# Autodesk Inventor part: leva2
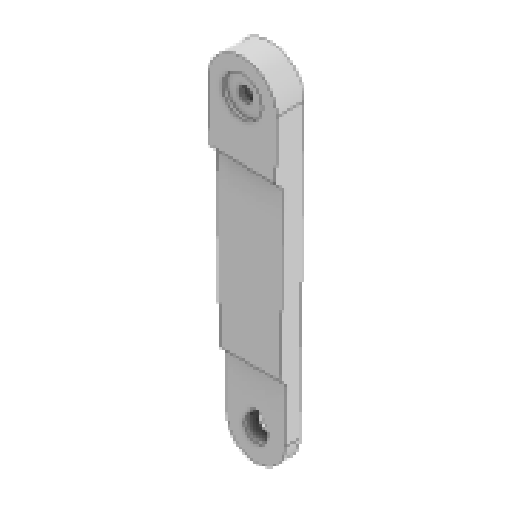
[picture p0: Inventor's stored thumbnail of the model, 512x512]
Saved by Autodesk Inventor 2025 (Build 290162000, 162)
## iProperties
Created: 2025-05
Part Number: leva2
Material: Plastica ABS
Document SubType Name: Modeling
Designer: R5800u
Density: 1.06 g/cm^3
Appearance: Liscia - Nero
Author: R5800u
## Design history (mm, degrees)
sketch "Schizzo1"
  geometry: L1 (-17.498, 149.708)-(-14.998, -0.25); L2 (17.498, 149.708)-(14.998, -0.25); L3 (0, 0)-(0, 150); A1 r 15 centre (0, 0) between (-14.998, -0.25) and (14.998, -0.25); A2 r 17.5 centre (0, 150) between (-17.498, 149.708) and (17.498, 149.708); 1 further point
  constraints: 6 end point, 4 point on circle, 4 tangent, 2 centre point, 2 coincident, 1 vertical
  dimensions: "d0" = 30 diameter of A1; "d1" = 35 diameter of A2; "d28" = 150 distance of L3.start L3.end
extrude "Estrusione1" new body sketch "Schizzo1" distance "d3" = 10; taper "d4" = 0 deg
sketch "Schizzo2"
  geometry: L1 (-17.498, 149.708)-(-14.998, -0.25) reference; L2 (14.998, -0.25)-(17.498, 149.708) reference; L3 (-17.498, 149.708)-(-14.998, -0.25) reference; L4 (-17.007, 120.279)-(16.998, 119.713); A1 r 15 centre (0, 0) between (-14.998, -0.25) and (14.998, -0.25) reference; A2 r 17.5 centre (0, 150) between (17.498, 149.708) and (-17.498, 149.708) reference; 2 further points
  constraints: 2 end point, 2 point on line, 1 perpendicular
  dimensions: "d5" = 30 distance from line of L4 A2.centre
extrude "Estrusione2" join sketch "Schizzo2" distance "d6" = 4; taper "d7" = 0 deg
sketch "Schizzo3"
  geometry: C1 r 10 at (0, 150); A1 r 17.5 centre (0, 150) between (17.498, 149.708) and (-17.498, 149.708) reference; 1 further point
  constraints: 1 centre point, 1 coincident
  dimensions: "d8" = 20 diameter of C1
extrude "Estrusione3" cut sketch "Schizzo3" distance "d9" = 2; taper "d10" = 0 deg
sketch "Schizzo4"
  geometry: C1 r 10 at (0, 0) reference; 2 further points
  constraints: 1 coincident
hole "Foro1" sketch "Schizzo4" at (0, 0) diameter "d11" = 3.2; stored, may be unused: countersink angle "d15" = 90 deg, drill point angle "d17" = 118 deg; dims "d12" = 6, "d13" = 7, "d14" = 3, "d16" = 8
chamfer "Smusso1" distance "d18" = 4; stored, may be unused: second distance "d19" = 2, angle "d20" = 45 deg
sketch "Schizzo5"
  geometry: 1 further point
hole "Foro2" sketch "Schizzo5" at (0, 0) diameter "d21" = 12; stored, may be unused: countersink angle "d25" = 90 deg, drill point angle "d27" = 118 deg; dims "d22" = 6, "d23" = 7, "d24" = 2, "d26" = 8
sketch "Schizzo6"
  geometry: L1 (-16.94, 116.278)-(16.931, 115.713) reference; L2 (-16.94, 116.278)-(-14.998, -0.25) reference; L3 (14.998, -0.25)-(16.931, 115.713) reference; L4 (0, 150)-(0, 0); L5 (15.502, 30)-(-15.502, 30); C1 r 6 at (0, 0) reference; C2 r 1.6 at (0, 150) reference; A1 r 15 centre (0, 0) between (-14.998, -0.25) and (14.998, -0.25) reference; 1 further point
  constraints: 4 end point, 2 point on line, 1 horizontal
  dimensions: "d34" = 30 distance from line of L5 point (0, 0)
extrude "Estrusione4" cut sketch "Schizzo6" distance "d29" = 3; taper "d30" = 0 deg
chamfer "Smusso2" distance "d31" = 3; stored, may be unused: second distance "d32" = 2, angle "d33" = 45 deg
sketch "Schizzo7"
  geometry: C1 r 2 at (0, 0) reference; A1 r 2.5 centre (0, 5.9) between (2.326, 4.984) and (-2.326, 4.984) reference; A2 r 5.5 centre (0, 0) between (-2.326, 4.984) and (2.326, 4.984) reference; A3 r 2.8 centre (0, 5.9) between (2.694, 5.136) and (-2.694, 5.136); A4 r 5.8 centre (0, 0) between (-2.694, 5.136) and (2.694, 5.136); 1 further point
  constraints: 4 point on circle, 2 centre point, 1 other
  dimensions: "d35" = 0.3 radial gap between concentric circles of A1 A3
extrude "Estrusione5" cut sketch "Schizzo7" distance "d36" = 3; taper "d37" = 0 deg
sketch "Schizzo8"
  geometry: A1 r 1 centre (0, -8.05) between (0.5, -8.916) and (-0.5, -8.916) reference; A2 r 1 centre (0, 19.35) between (-0.5, 20.216) and (0.5, 20.216) reference; 1 further point
  node "Riferimento2"
  node "Riferimento3"
sketch "Schizzo9"
  geometry: C1 r 1.25 at (-2.037, 156.697) reference; C2 r 1.25 at (6.697, 152.037) reference; C3 r 1.25 at (2.037, 143.303) reference; C4 r 1.25 at (-6.697, 147.963) reference; 1 further point
hole "Foro3" sketch "Schizzo9" at (-6.697, 147.963), (2.037, 143.303), (6.697, 152.037), (-2.037, 156.697) diameter "d38" = 3.2; stored, may be unused: countersink angle "d42" = 90 deg, drill point angle "d44" = 118 deg; dims "d39" = 6, "d40" = 11, "d41" = 2.6, "d43" = 8
sketch "Schizzo10"
  geometry: C1 r 1.6 at (0, 150) reference; 2 further points
  constraints: 1 coincident
hole "Foro4" sketch "Schizzo10" at (0, 150) diameter "d45" = 3.2; stored, may be unused: countersink angle "d49" = 90 deg, drill point angle "d51" = 118 deg; dims "d46" = 6, "d47" = 6, "d48" = 2.6, "d50" = 8
hole "Foro5" sketch "Schizzo8" diameter "d52" = 2.5; stored, may be unused: countersink angle "d56" = 90 deg, drill point angle "d58" = 118 deg; dims "d53" = 6, "d54" = 6, "d55" = 2.6, "d57" = 8
chamfer "Smusso3" distance "d59" = 2; stored, may be unused: second distance "d60" = 2, angle "d61" = 45 deg
node "Solido1"
node "Linea chiusa proiettata1"
node "Linea chiusa proiettata2"
node "Riferimento1"
node "Riferimento4"
node "Riferimento5"
node "Riferimento6"
node "Riferimento7"
